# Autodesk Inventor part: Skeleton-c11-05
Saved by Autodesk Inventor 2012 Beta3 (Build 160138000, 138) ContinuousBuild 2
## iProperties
Created: 2011-01
Part Number: Skeleton-c11-05
Material: Default
Document SubType Name: Modeling
Designer: Beta-8540w
Density: 1 g/cm^3
_SkeletonDoc: Frame Skeleton File
_Version: 15.0.0
Author: Beta-8540w
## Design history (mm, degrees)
sketch "Reference Skeleton"
  geometry: L1 through (404.523, 1164.395) direction (1, 0); L2 through (325.691, 1070.446) direction (1, 0); 34 other entities
  constraints: 10 horizontal
